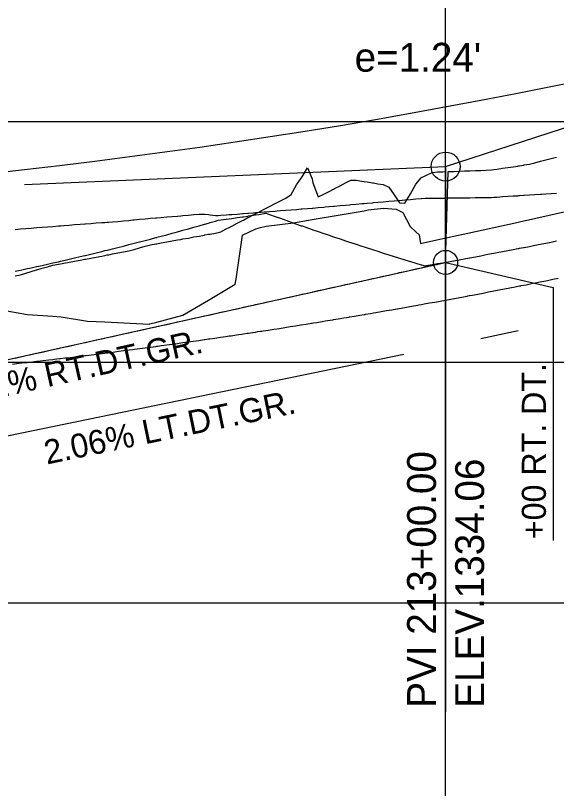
# Model space of a CAD drawing. Extents: x 1371206 to 1374178, y 379328 to 381511.
# Drawn here: x 1372455.2 to 1372567.7, y 379509.7 to 379670.4 of the extents above; entities that cross this region are included whole.
import ezdxf

# ---------------------------------------------------------------- set-up
doc = ezdxf.new("R2010")
doc.units = 0
for name, color, linetype in [('37', 7, 'Continuous'), ('R_Exist Surface', 7, 'Continuous'), ('R_Profile Work Left', 7, 'Continuous'), ('R_Profile Work Right', 7, 'Continuous'), ('R_Vert Alg', 7, 'Continuous'), ('R_Vert Alg Annot', 7, 'Continuous')]:
    doc.layers.add(name, color=color, linetype=linetype)

msp = doc.modelspace()

# ---------------------------------------------------------------- linework, layer by layer
at = {"layer": '37'}
for p, q in [((1372544.63, 379348.35), (1372544.63, 379798.35)), ((1371244.63, 379648.35), (1374144.63, 379648.35)), ((1371244.63, 379598.35), (1372944.63, 379598.35)), ((1371244.63, 379598.35), (1374144.63, 379598.35)), ((1371244.63, 379548.35), (1374144.63, 379548.35))]:
    msp.add_line(p, q, dxfattribs=at)
at = {"layer": 'R_Exist Surface'}
msp.add_lwpolyline([(1372452.26, 379609.23), (1372457.78, 379608.2), (1372463.04, 379607.85), (1372464.77, 379607.72), (1372470.25, 379606.86), (1372473.81, 379606.71), (1372483, 379606.22), (1372483.14, 379606.26), (1372484.59, 379606.64), (1372490.04, 379608.08), (1372495.36, 379611.22), (1372500.88, 379614.52), (1372501.13, 379615.57), (1372502.46, 379624.71), (1372505.21, 379626.05), (1372506.14, 379626.27), (1372507.34, 379626.57), (1372512.99, 379627.25), (1372516.91, 379627.93), (1372527.69, 379629.79), (1372528.57, 379629.95), (1372531.76, 379630.32), (1372534.39, 379630.12), (1372535.72, 379629.45), (1372537.24, 379626.49), (1372538.46, 379625.4), (1372539.17, 379624.78), (1372539.44, 379622.98), (1372542.81, 379623.75), (1372549.24, 379625.11), (1372557.87, 379626.99), (1372559.46, 379627.36), (1372560.01, 379627.48), (1372570.79, 379629.89)], dxfattribs=at)
at = {"layer": 'R_Profile Work Left'}
for points in [[(1372455.16, 379625.92), (1372456.29, 379626), (1372457.41, 379626.08), (1372458.54, 379626.18), (1372459.63, 379626.27), (1372459.66, 379626.27), (1372460.79, 379626.36), (1372461.91, 379626.45), (1372463.04, 379626.54), (1372463.04, 379626.54), (1372464.16, 379626.64), (1372464.63, 379626.67), (1372465.29, 379626.73), (1372466.41, 379626.82), (1372467.54, 379626.91), (1372468.67, 379627), (1372469.63, 379627.07), (1372469.79, 379627.08), (1372470.92, 379627.16), (1372472.04, 379627.24), (1372473.17, 379627.32), (1372473.81, 379627.37), (1372474.29, 379627.41), (1372474.63, 379627.43), (1372475.42, 379627.49), (1372476.54, 379627.57), (1372477.67, 379627.68), (1372478.79, 379627.79), (1372479.63, 379627.88), (1372479.92, 379627.91), (1372481.05, 379628.03), (1372482.17, 379628.12), (1372483.3, 379628.22), (1372484.42, 379628.31), (1372484.59, 379628.33), (1372484.63, 379628.33), (1372485.55, 379628.41), (1372486.67, 379628.5), (1372487.8, 379628.6), (1372488.92, 379628.69), (1372489.63, 379628.75), (1372490.05, 379628.79), (1372491.17, 379628.88), (1372492.3, 379628.97), (1372493.42, 379629.06), (1372494.55, 379629.05), (1372494.63, 379629.05), (1372495.36, 379629.02), (1372495.68, 379628.96), (1372496.8, 379628.78), (1372497.36, 379628.82), (1372497.93, 379628.85), (1372499.05, 379628.93), (1372499.63, 379628.97), (1372500.18, 379629.02), (1372501.3, 379629.1), (1372502.43, 379629.19), (1372502.63, 379629.21), (1372503.55, 379629.28), (1372503.66, 379629.29), (1372504.63, 379629.37), (1372504.68, 379629.37), (1372505.16, 379629.41), (1372505.8, 379629.46), (1372506.14, 379629.49), (1372506.93, 379629.55), (1372507.36, 379629.58), (1372508.05, 379629.64), (1372509.18, 379629.72), (1372509.63, 379629.76), (1372510.31, 379629.81), (1372511.43, 379629.9), (1372512.56, 379629.99), (1372513.68, 379630.07), (1372514.63, 379630.15), (1372514.81, 379630.16), (1372515.93, 379630.25), (1372516.91, 379630.32), (1372517.06, 379630.33), (1372518.18, 379630.45), (1372519.31, 379630.55), (1372519.63, 379630.58), (1372520.43, 379630.65), (1372521.35, 379630.74), (1372521.56, 379630.76), (1372522.69, 379630.86), (1372523.81, 379630.96), (1372524.63, 379631.04), (1372524.94, 379631.06), (1372526.06, 379631.17), (1372527.19, 379631.27), (1372527.69, 379631.31), (1372528.31, 379631.36), (1372529.44, 379631.46), (1372529.63, 379631.47), (1372530.56, 379631.55), (1372531.69, 379631.65), (1372532.81, 379631.74), (1372533.94, 379631.84), (1372534.63, 379631.9), (1372535.06, 379631.94), (1372536.19, 379632.03), (1372537.32, 379632.13), (1372538.44, 379632.23), (1372538.46, 379632.23), (1372539.57, 379632.32), (1372539.63, 379632.32), (1372540.36, 379632.37), (1372540.69, 379632.37), (1372541.82, 379632.39), (1372542.94, 379632.41), (1372544.07, 379632.42), (1372544.63, 379632.43), (1372545.19, 379632.44), (1372546.32, 379632.46), (1372547.44, 379632.47), (1372548.57, 379632.49), (1372548.83, 379632.49), (1372549.24, 379632.49), (1372549.63, 379632.5), (1372549.69, 379632.5), (1372550.82, 379632.51), (1372551.95, 379632.52), (1372553.07, 379632.53), (1372554.2, 379632.54), (1372554.63, 379632.57), (1372555.32, 379632.63), (1372556.45, 379632.71), (1372557.57, 379632.78), (1372558.7, 379632.85), (1372559.63, 379632.91), (1372559.82, 379632.93), (1372560.01, 379632.94), (1372560.83, 379632.99), (1372560.95, 379633), (1372562.07, 379633.07), (1372563.2, 379633.14), (1372564.32, 379633.21), (1372564.63, 379633.23), (1372565.45, 379633.28), (1372566.58, 379633.35), (1372567.7, 379633.42)], [(1372454.63, 379597.93), (1372455.46, 379598.03), (1372456.57, 379598.15), (1372457.69, 379598.28), (1372458.24, 379598.34), (1372458.8, 379598.4), (1372459.63, 379598.5), (1372459.92, 379598.53), (1372461.03, 379598.66), (1372462.15, 379598.79), (1372463.04, 379598.9), (1372463.26, 379598.92), (1372463.29, 379598.93), (1372464.38, 379599.06), (1372464.63, 379599.09), (1372465.49, 379599.19), (1372466.6, 379599.32), (1372467.72, 379599.46), (1372468.83, 379599.6), (1372469.63, 379599.69), (1372469.95, 379599.73), (1372471.06, 379599.87), (1372472.18, 379600.01), (1372473.29, 379600.15), (1372473.81, 379600.22), (1372474.07, 379600.25), (1372474.41, 379600.29), (1372474.63, 379600.32), (1372475.52, 379600.43), (1372476.64, 379600.58), (1372477.75, 379600.72), (1372478.87, 379600.87), (1372479.63, 379600.97), (1372479.98, 379601.01), (1372481.1, 379601.16), (1372482.21, 379601.31), (1372483.32, 379601.46), (1372484.44, 379601.61), (1372484.59, 379601.63), (1372484.63, 379601.64), (1372484.85, 379601.67), (1372485.55, 379601.76), (1372486.67, 379601.91), (1372487.78, 379602.07), (1372488.9, 379602.22), (1372489.63, 379602.32), (1372490.01, 379602.38), (1372491.13, 379602.53), (1372492.24, 379602.69), (1372493.36, 379602.85), (1372494.47, 379603.01), (1372494.63, 379603.03), (1372495.36, 379603.14), (1372495.59, 379603.17), (1372495.63, 379603.18), (1372496.7, 379603.33), (1372497.82, 379603.49), (1372498.93, 379603.66), (1372499.63, 379603.76), (1372500.04, 379603.82), (1372501.16, 379603.99), (1372501.67, 379604.06), (1372502.27, 379604.15), (1372502.63, 379604.21), (1372503.39, 379604.32), (1372503.66, 379604.36), (1372504.5, 379604.49), (1372504.59, 379604.5), (1372504.63, 379604.51), (1372505.16, 379604.59), (1372505.62, 379604.66), (1372506.14, 379604.74), (1372506.41, 379604.78), (1372506.73, 379604.83), (1372507.85, 379605), (1372508.96, 379605.18), (1372509.63, 379605.28), (1372510.08, 379605.35), (1372511.19, 379605.52), (1372512.31, 379605.7), (1372513.42, 379605.88), (1372514.53, 379606.05), (1372514.63, 379606.07), (1372515.65, 379606.23), (1372516.76, 379606.41), (1372516.91, 379606.44), (1372517.19, 379606.48), (1372517.88, 379606.59), (1372518.99, 379606.77), (1372519.63, 379606.88), (1372520.11, 379606.96), (1372521.22, 379607.14), (1372521.35, 379607.16), (1372522.34, 379607.33), (1372523.45, 379607.51), (1372524.57, 379607.7), (1372524.63, 379607.71), (1372525.68, 379607.89), (1372526.8, 379608.07), (1372527.69, 379608.23), (1372527.91, 379608.26), (1372527.98, 379608.27), (1372529.03, 379608.45), (1372529.63, 379608.56), (1372530.14, 379608.65), (1372531.25, 379608.84), (1372532.37, 379609.03), (1372533.48, 379609.23), (1372534.6, 379609.42), (1372534.63, 379609.43), (1372535.71, 379609.62), (1372536.83, 379609.82), (1372537.94, 379610.02), (1372538.46, 379610.11), (1372538.76, 379610.16), (1372539.06, 379610.22), (1372539.63, 379610.32), (1372540.17, 379610.42), (1372541.29, 379610.62), (1372542.4, 379610.82), (1372543.52, 379611.03), (1372544.63, 379611.23), (1372545.75, 379611.44), (1372546.86, 379611.64), (1372547.97, 379611.85), (1372549.09, 379612.06), (1372549.24, 379612.09), (1372549.54, 379612.14), (1372549.63, 379612.16), (1372550.2, 379612.27), (1372551.32, 379612.48), (1372552.43, 379612.69), (1372553.55, 379612.91), (1372554.63, 379613.11), (1372554.66, 379613.12), (1372555.78, 379613.33), (1372556.89, 379613.55), (1372558.01, 379613.77), (1372559.12, 379613.99), (1372559.63, 379614.08), (1372560.01, 379614.16), (1372560.24, 379614.2), (1372560.32, 379614.22), (1372561.35, 379614.42), (1372562.46, 379614.64), (1372563.58, 379614.87), (1372564.63, 379615.08), (1372564.69, 379615.09), (1372565.81, 379615.31), (1372566.92, 379615.54), (1372568.04, 379615.76)]]:
    msp.add_lwpolyline(points, dxfattribs=at)
at = {"layer": 'R_Profile Work Right'}
for points in [[(1372544.63, 379619.05), (1372545.19, 379637.93), (1372546.32, 379637.97), (1372547.44, 379638.01), (1372548.57, 379638.05), (1372548.83, 379638.06), (1372549.24, 379638.07), (1372549.63, 379638.09), (1372549.69, 379638.09), (1372550.82, 379638.13), (1372551.95, 379638.17), (1372553.07, 379638.21), (1372554.2, 379638.28), (1372554.63, 379638.34), (1372555.32, 379638.44), (1372556.45, 379638.61), (1372557.57, 379638.77), (1372558.7, 379638.93), (1372559.63, 379639.07), (1372559.82, 379639.1), (1372560.01, 379639.13), (1372560.83, 379639.27), (1372560.95, 379639.29), (1372562.07, 379639.48), (1372563.2, 379639.77), (1372564.32, 379640.05), (1372564.63, 379640.13), (1372565.45, 379640.34), (1372566.58, 379640.63), (1372567.7, 379640.91)], [(1372455.16, 379616.26), (1372456.29, 379616.5), (1372457.41, 379616.83), (1372458.54, 379617.17), (1372459.63, 379617.49), (1372459.66, 379617.5), (1372460.79, 379617.83), (1372461.91, 379618.16), (1372463.04, 379618.45), (1372463.04, 379618.45), (1372464.16, 379618.66), (1372464.63, 379618.75), (1372465.29, 379618.88), (1372466.41, 379619.09), (1372467.54, 379619.31), (1372468.67, 379619.52), (1372469.63, 379619.7), (1372469.79, 379619.73), (1372470.92, 379619.95), (1372472.04, 379620.16), (1372473.17, 379620.38), (1372473.81, 379620.5), (1372474.29, 379620.59), (1372474.63, 379620.65), (1372475.42, 379620.8), (1372476.54, 379621.02), (1372477.67, 379621.24), (1372478.79, 379621.48), (1372479.63, 379621.66), (1372479.92, 379621.72), (1372481.05, 379622.06), (1372482.17, 379622.41), (1372483.3, 379622.68), (1372484.42, 379622.89), (1372484.59, 379622.92), (1372484.63, 379622.93), (1372485.55, 379623.09), (1372486.67, 379623.3), (1372487.8, 379623.51), (1372488.92, 379623.71), (1372489.63, 379623.84), (1372490.05, 379623.92), (1372491.17, 379624.12), (1372492.3, 379624.33), (1372493.42, 379624.53), (1372494.55, 379624.74), (1372494.63, 379624.75), (1372495.36, 379624.89), (1372495.68, 379624.94), (1372496.8, 379625.15), (1372497.36, 379625.25), (1372497.93, 379625.41), (1372499.05, 379626), (1372499.63, 379626.3), (1372500.18, 379626.58), (1372501.3, 379627.17), (1372502.43, 379627.76), (1372502.63, 379627.86), (1372503.55, 379628.35), (1372503.66, 379628.4), (1372504.63, 379628.91), (1372504.68, 379628.93), (1372505.16, 379629.19), (1372505.8, 379629.52), (1372506.14, 379629.7), (1372506.93, 379630.11), (1372507.36, 379630.33), (1372508.05, 379630.69), (1372509.18, 379631.26), (1372509.63, 379631.48), (1372510.31, 379631.82), (1372511.43, 379632.39), (1372512.56, 379633.17), (1372513.68, 379635.2), (1372514.63, 379636.56), (1372514.81, 379636.85), (1372515.93, 379638.73), (1372516.91, 379636.38), (1372517.06, 379635.56), (1372518.18, 379632.7), (1372519.31, 379633.24), (1372519.63, 379633.39), (1372520.43, 379633.81), (1372521.35, 379634.28), (1372521.56, 379634.39), (1372522.69, 379634.98), (1372523.81, 379635.56), (1372524.63, 379635.99), (1372524.94, 379636.15), (1372526.06, 379636.14), (1372527.19, 379635.95), (1372527.69, 379635.87), (1372528.31, 379635.77), (1372529.44, 379635.58), (1372529.63, 379635.55), (1372530.56, 379635.4), (1372531.69, 379635.23), (1372532.81, 379634.67), (1372533.94, 379633.06), (1372534.63, 379632.06), (1372535.06, 379631.44), (1372536.19, 379631.33), (1372537.32, 379633.31), (1372538.44, 379635.3), (1372538.46, 379635.34), (1372539.57, 379636.62), (1372539.63, 379636.66), (1372540.36, 379637.02), (1372540.69, 379637.19), (1372541.82, 379637.76), (1372542.94, 379637.86), (1372544.07, 379637.9), (1372544.63, 379637.91)], [(1372455.16, 379617.22), (1372456.29, 379617.46), (1372457.41, 379617.7), (1372458.54, 379617.94), (1372459.63, 379618.18), (1372459.66, 379618.19), (1372460.79, 379618.44), (1372461.91, 379618.69), (1372463.04, 379618.94), (1372463.04, 379618.94), (1372464.16, 379619.2), (1372464.63, 379619.31), (1372465.29, 379619.46), (1372466.41, 379619.72), (1372467.54, 379619.98), (1372468.67, 379620.25), (1372469.63, 379620.47), (1372469.79, 379620.51), (1372470.92, 379620.78), (1372472.04, 379621.06), (1372473.17, 379621.33), (1372473.81, 379621.49), (1372474.29, 379621.61), (1372474.63, 379621.69), (1372475.42, 379621.89), (1372476.54, 379622.17), (1372477.67, 379622.45), (1372478.79, 379622.74), (1372479.63, 379622.95), (1372479.92, 379623.03), (1372481.05, 379623.32), (1372482.17, 379623.61), (1372483.3, 379623.91), (1372484.42, 379624.2), (1372484.59, 379624.25), (1372484.63, 379624.26), (1372485.55, 379624.5), (1372486.67, 379624.81), (1372487.8, 379625.11), (1372488.92, 379625.42), (1372489.63, 379625.61), (1372490.05, 379625.73), (1372491.17, 379626.04), (1372492.3, 379626.36), (1372493.42, 379626.67), (1372494.55, 379626.99), (1372494.63, 379627.01), (1372495.36, 379627.22), (1372495.68, 379627.31), (1372496.8, 379627.64), (1372497.36, 379627.8), (1372497.93, 379627.88), (1372499.05, 379628.03), (1372499.63, 379628.11), (1372500.18, 379628.19), (1372501.3, 379628.35), (1372502.43, 379628.52), (1372502.63, 379628.55), (1372503.55, 379628.69), (1372503.66, 379628.7), (1372504.63, 379628.85), (1372504.68, 379628.85), (1372505.16, 379628.93), (1372505.8, 379629.03), (1372506.14, 379629.08), (1372506.93, 379629.2), (1372507.36, 379629.27), (1372508.05, 379629.01), (1372509.18, 379628.61), (1372509.63, 379628.45), (1372510.31, 379628.21), (1372511.43, 379627.8), (1372512.56, 379627.41), (1372513.68, 379627.01), (1372514.63, 379626.68), (1372514.81, 379626.62), (1372515.93, 379626.22), (1372516.91, 379625.89), (1372517.06, 379625.84), (1372518.18, 379625.45), (1372519.31, 379625.07), (1372519.63, 379624.96), (1372520.43, 379624.68), (1372521.35, 379624.38), (1372521.56, 379624.3), (1372522.69, 379623.93), (1372523.81, 379623.55), (1372524.63, 379623.28), (1372524.94, 379623.18), (1372526.06, 379622.81), (1372527.19, 379622.44), (1372527.69, 379622.28), (1372528.31, 379622.08), (1372529.44, 379621.72), (1372529.63, 379621.66), (1372530.56, 379621.36), (1372531.69, 379621), (1372532.81, 379620.65), (1372533.94, 379620.29), (1372534.63, 379620.08), (1372535.06, 379619.94), (1372536.19, 379619.59), (1372537.32, 379619.25), (1372538.44, 379618.91), (1372538.46, 379618.9), (1372539.57, 379618.56), (1372539.63, 379618.55), (1372540.36, 379618.33), (1372540.69, 379618.39), (1372541.82, 379618.59), (1372542.94, 379618.79), (1372544.07, 379618.99), (1372544.63, 379619.09), (1372545.19, 379619.2), (1372546.32, 379619.4), (1372547.44, 379619.61), (1372548.57, 379619.82), (1372548.83, 379619.86), (1372549.24, 379619.94), (1372549.63, 379620.01), (1372549.69, 379620.02), (1372550.82, 379620.23), (1372551.95, 379620.44), (1372553.07, 379620.66), (1372554.2, 379620.87), (1372554.63, 379620.95), (1372555.32, 379621.08), (1372556.45, 379621.3), (1372557.57, 379621.51), (1372558.7, 379621.73), (1372559.63, 379621.91), (1372559.82, 379621.95), (1372560.01, 379621.98), (1372560.83, 379622.14), (1372560.95, 379622.17), (1372562.07, 379622.38), (1372563.2, 379622.61), (1372564.32, 379622.83), (1372564.63, 379622.89), (1372565.45, 379623.05), (1372566.58, 379623.27), (1372567.7, 379623.5)], [(1372455.16, 379599.18), (1372456.29, 379599.43), (1372457.41, 379599.68), (1372458.54, 379599.93), (1372459.63, 379600.18), (1372459.66, 379600.18), (1372460.79, 379600.43), (1372461.91, 379600.68), (1372463.04, 379600.93), (1372463.04, 379600.93), (1372464.16, 379601.18), (1372464.63, 379601.29), (1372465.29, 379601.43), (1372466.41, 379601.68), (1372467.54, 379601.93), (1372468.67, 379602.18), (1372469.63, 379602.4), (1372469.79, 379602.43), (1372470.92, 379602.68), (1372472.04, 379602.93), (1372473.17, 379603.18), (1372473.81, 379603.32), (1372474.29, 379603.43), (1372474.63, 379603.51), (1372475.42, 379603.68), (1372476.54, 379603.93), (1372477.67, 379604.18), (1372478.79, 379604.43), (1372479.63, 379604.62), (1372479.92, 379604.68), (1372481.05, 379604.93), (1372482.17, 379605.18), (1372483.3, 379605.43), (1372484.42, 379605.68), (1372484.59, 379605.72), (1372484.63, 379605.73), (1372485.55, 379605.93), (1372486.67, 379606.18), (1372487.8, 379606.43), (1372488.92, 379606.68), (1372489.63, 379606.84), (1372490.05, 379606.93), (1372491.17, 379607.18), (1372492.3, 379607.43), (1372493.42, 379607.68), (1372494.55, 379607.93), (1372494.63, 379607.95), (1372495.36, 379608.11), (1372495.68, 379608.18), (1372496.8, 379608.43), (1372497.36, 379608.55), (1372497.93, 379608.68), (1372499.05, 379608.93), (1372499.63, 379609.06), (1372500.18, 379609.18), (1372501.3, 379609.43), (1372502.43, 379609.68), (1372502.63, 379609.72), (1372503.55, 379609.93), (1372503.66, 379609.95), (1372504.63, 379610.17), (1372504.68, 379610.18), (1372505.16, 379610.29), (1372505.8, 379610.43), (1372506.14, 379610.5), (1372506.93, 379610.68), (1372507.36, 379610.77), (1372508.05, 379610.93), (1372509.18, 379611.18), (1372509.63, 379611.28), (1372510.31, 379611.43), (1372511.43, 379611.68), (1372512.56, 379611.93), (1372513.68, 379612.18), (1372514.63, 379612.39), (1372514.81, 379612.43), (1372515.93, 379612.68), (1372516.91, 379612.9), (1372517.06, 379612.93), (1372518.18, 379613.18), (1372519.31, 379613.43), (1372519.63, 379613.5), (1372520.43, 379613.68), (1372521.35, 379613.88), (1372521.56, 379613.93), (1372522.69, 379614.18), (1372523.81, 379614.43), (1372524.63, 379614.61), (1372524.94, 379614.68), (1372526.06, 379614.93), (1372527.19, 379615.18), (1372527.69, 379615.29), (1372528.31, 379615.43), (1372529.44, 379615.68), (1372529.63, 379615.72), (1372530.56, 379615.93), (1372531.69, 379616.18), (1372532.81, 379616.43), (1372533.94, 379616.68), (1372534.63, 379616.83), (1372535.06, 379616.93), (1372536.19, 379617.18), (1372537.32, 379617.43), (1372538.44, 379617.68), (1372538.46, 379617.68), (1372539.57, 379617.93), (1372539.63, 379617.94), (1372540.36, 379618.1), (1372540.69, 379618.18), (1372541.82, 379618.43), (1372542.94, 379618.68), (1372544.07, 379618.93), (1372544.63, 379619.05)]]:
    msp.add_lwpolyline(points, dxfattribs=at)
at = {"layer": 'R_Vert Alg'}
for p, q in [((1372544.63, 379638.95), (1372632.13, 379667.48)), ((1372457.13, 379635.24), (1372544.63, 379638.95)), ((1372394.13, 379585.63), (1372544.63, 379619.05)), ((1372551.93, 379603.27), (1372559.73, 379604.87)), ((1372439.63, 379580.15), (1372535.92, 379599.97))]:
    msp.add_line(p, q, dxfattribs=at)
msp.add_lwpolyline([(1372449.84, 379637.54), (1372457.13, 379638.34), (1372464.42, 379639.19), (1372471.71, 379640.08), (1372479.01, 379641.02), (1372486.3, 379641.99), (1372493.59, 379643.01), (1372500.88, 379644.08), (1372508.17, 379645.18), (1372515.46, 379646.33), (1372522.76, 379647.52), (1372530.05, 379648.76), (1372537.34, 379650.04), (1372551.92, 379652.73), (1372559.21, 379654.13), (1372566.51, 379655.58), (1372573.8, 379657.08)], dxfattribs=at)
for centre, radius in [((1372544.63, 379638.95), 3), ((1372544.63, 379619.05), 2.5)]:
    msp.add_circle(centre, radius, dxfattribs=at)
at = {"layer": 'R_Vert Alg Annot'}
msp.add_line((1372544.63, 379638.95), (1372544.63, 379525.67), dxfattribs=at)
msp.add_lwpolyline([(1372544.63, 379619.05), (1372566.97, 379613.81), (1372566.97, 379561.28)], dxfattribs=at)

# ---------------------------------------------------------------- texts
msp.add_text("e=1.24'", height=6, dxfattribs=at).set_placement((1372525.73, 379658.67))
for s, height, rotation, p in [('2.22% RT.DT.GR.', 5, 12.5204, (1372441.56, 379588.61)), ('+00 RT. DT.', 5, 90, (1372565.47, 379561.55)), ('2.06% LT.DT.GR.', 5, 11.6321, (1372461.76, 379577.05)), ('PVI 213+00.00', 6, 90, (1372542.63, 379526.53)), ('ELEV.1334.06', 6, 90, (1372552.63, 379526.53))]:
    msp.add_text(s, height=height, rotation=rotation, dxfattribs=at).set_placement(p)

doc.saveas('drawing.dxf')
